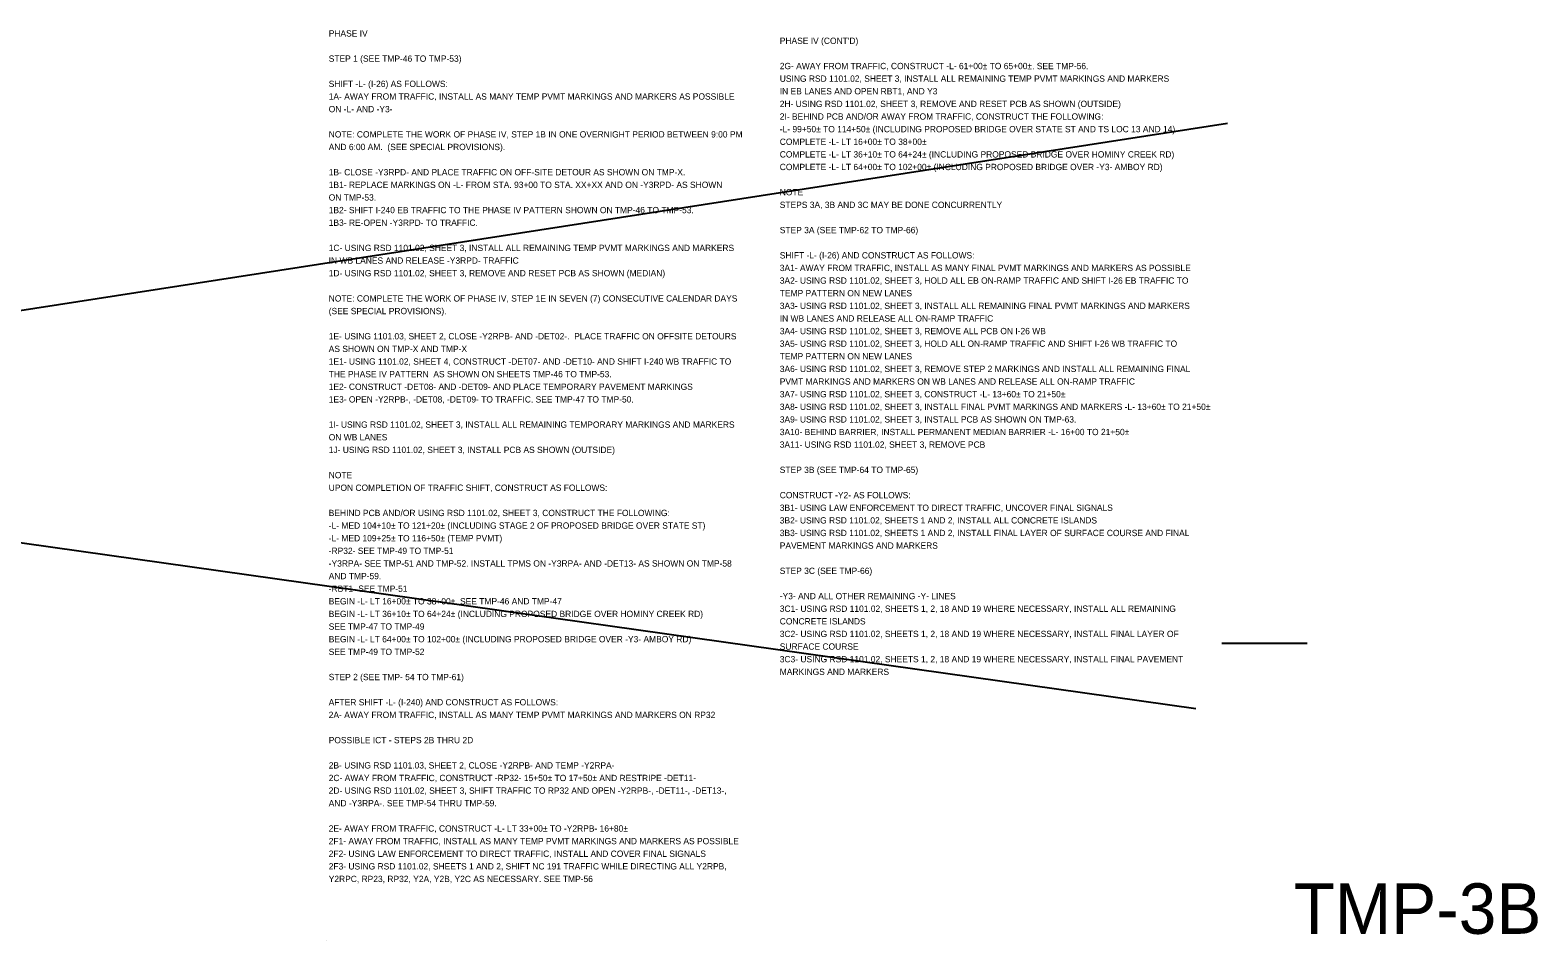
# Model space of a CAD drawing. Extents: x 2483905 to 2494512, y 366160 to 372330.
# Drawn here: x 2490709 to 2492380, y 371319 to 372330 of the extents above; entities that cross this region are included whole.
import ezdxf

# ---------------------------------------------------------------- set-up
doc = ezdxf.new("R2010")
doc.units = 0
doc.layers.add('TC SHEET BORDER LINE THIN', color=7, linetype='Continuous')
doc.layers.add('TC SHEET LAYOUT SHAPE', color=7, linetype='Continuous')

msp = doc.modelspace()

# ---------------------------------------------------------------- linework, layer by layer
at = {"layer": 'TC SHEET BORDER LINE THIN'}
for p, q in [((2486912.1, 372296.4), (2492000.8, 371577)), ((2486863.2, 371423.3), (2492035.7, 372226.5)), ((2492029.6, 371649.5), (2492124, 371649.5)), ((2491037.3, 371319.4), (2491037.3, 371319.4))]:
    msp.add_line(p, q, dxfattribs=at)

# ---------------------------------------------------------------- texts
for s, p in [('PHASE IV', (2491039.5, 372322.6)), ("PHASE IV (CONT'D)", (2491539.5, 372314.4)), ('STEP 1 (SEE TMP-46 TO TMP-53)', (2491039.5, 372294.6)), ('2G- AWAY FROM TRAFFIC, CONSTRUCT -L- 61+00± TO 65+00±. SEE TMP-56.', (2491539.5, 372286.4)), ('SHIFT -L- (I-26) AS FOLLOWS:', (2491039.5, 372266.6)), ('USING RSD 1101.02, SHEET 3, INSTALL ALL REMAINING TEMP PVMT MARKINGS AND MARKERS', (2491539.5, 372272.4)), ('1A- AWAY FROM TRAFFIC, INSTALL AS MANY TEMP PVMT MARKINGS AND MARKERS AS POSSIBLE', (2491039.5, 372252.6)), ('IN EB LANES AND OPEN RBT1, AND Y3', (2491539.5, 372258.4)), ('ON -L- AND -Y3-', (2491039.5, 372238.6)), ('2H- USING RSD 1101.02, SHEET 3, REMOVE AND RESET PCB AS SHOWN (OUTSIDE)', (2491539.5, 372244.4)), ('2I- BEHIND PCB AND/OR AWAY FROM TRAFFIC, CONSTRUCT THE FOLLOWING:', (2491539.5, 372230.4)), ('-L- 99+50± TO 114+50± (INCLUDING PROPOSED BRIDGE OVER STATE ST AND TS LOC 13 AND 14)', (2491539.5, 372216.4)), ('NOTE: COMPLETE THE WORK OF PHASE IV, STEP 1B IN ONE OVERNIGHT PERIOD BETWEEN 9:00 PM', (2491039.5, 372210.6)), ('COMPLETE -L- LT 16+00± TO 38+00±', (2491539.5, 372202.4)), ('AND 6:00 AM.  (SEE SPECIAL PROVISIONS).', (2491039.5, 372196.6)), ('COMPLETE -L- LT 36+10± TO 64+24± (INCLUDING PROPOSED BRIDGE OVER HOMINY CREEK RD)', (2491539.5, 372188.4)), ('1B- CLOSE -Y3RPD- AND PLACE TRAFFIC ON OFF-SITE DETOUR AS SHOWN ON TMP-X.', (2491039.5, 372168.6)), ('COMPLETE -L- LT 64+00± TO 102+00± (INCLUDING PROPOSED BRIDGE OVER -Y3- AMBOY RD)', (2491539.5, 372174.4)), ('1B1- REPLACE MARKINGS ON -L- FROM STA. 93+00 TO STA. XX+XX AND ON -Y3RPD- AS SHOWN', (2491039.5, 372154.6)), ('ON TMP-53.', (2491039.5, 372140.6)), ('NOTE', (2491539.5, 372146.4)), ('1B2- SHIFT I-240 EB TRAFFIC TO THE PHASE IV PATTERN SHOWN ON TMP-46 TO TMP-53.', (2491039.5, 372126.6)), ('STEPS 3A, 3B AND 3C MAY BE DONE CONCURRENTLY', (2491539.5, 372132.4)), ('1B3- RE-OPEN -Y3RPD- TO TRAFFIC.', (2491039.5, 372112.6)), ('STEP 3A (SEE TMP-62 TO TMP-66)', (2491539.5, 372104.4)), ('1C- USING RSD 1101.02, SHEET 3, INSTALL ALL REMAINING TEMP PVMT MARKINGS AND MARKERS', (2491039.5, 372084.6)), ('IN WB LANES AND RELEASE -Y3RPD- TRAFFIC', (2491039.5, 372070.6)), ('SHIFT -L- (I-26) AND CONSTRUCT AS FOLLOWS:', (2491539.5, 372076.4)), ('1D- USING RSD 1101.02, SHEET 3, REMOVE AND RESET PCB AS SHOWN (MEDIAN)', (2491039.5, 372056.6)), ('3A1- AWAY FROM TRAFFIC, INSTALL AS MANY FINAL PVMT MARKINGS AND MARKERS AS POSSIBLE', (2491539.5, 372062.4)), ('TEMP PATTERN ON NEW LANES', (2491539.5, 372034.4)), ('3A2- USING RSD 1101.02, SHEET 3, HOLD ALL EB ON-RAMP TRAFFIC AND SHIFT I-26 EB TRAFFIC TO', (2491539.5, 372048.4)), ('NOTE: COMPLETE THE WORK OF PHASE IV, STEP 1E IN SEVEN (7) CONSECUTIVE CALENDAR DAYS', (2491039.5, 372028.6)), ('3A3- USING RSD 1101.02, SHEET 3, INSTALL ALL REMAINING FINAL PVMT MARKINGS AND MARKERS', (2491539.5, 372020.4)), ('(SEE SPECIAL PROVISIONS).', (2491039.5, 372014.6)), ('IN WB LANES AND RELEASE ALL ON-RAMP TRAFFIC', (2491539.5, 372006.4)), ('1E- USING 1101.03, SHEET 2, CLOSE -Y2RPB- AND -DET02-.  PLACE TRAFFIC ON OFFSITE DETOURS', (2491039.5, 371986.6)), ('3A4- USING RSD 1101.02, SHEET 3, REMOVE ALL PCB ON I-26 WB', (2491539.5, 371992.4)), ('AS SHOWN ON TMP-X AND TMP-X ', (2491039.5, 371972.6)), ('3A5- USING RSD 1101.02, SHEET 3, HOLD ALL ON-RAMP TRAFFIC AND SHIFT I-26 WB TRAFFIC TO', (2491539.5, 371978.4)), ('1E1- USING 1101.02, SHEET 4, CONSTRUCT -DET07- AND -DET10- AND SHIFT I-240 WB TRAFFIC TO', (2491039.5, 371958.6)), ('TEMP PATTERN ON NEW LANES', (2491539.5, 371964.4)), ('3A6- USING RSD 1101.02, SHEET 3, REMOVE STEP 2 MARKINGS AND INSTALL ALL REMAINING FINAL', (2491539.5, 371950.4)), ('THE PHASE IV PATTERN  AS SHOWN ON SHEETS TMP-46 TO TMP-53.', (2491039.5, 371944.6)), ('PVMT MARKINGS AND MARKERS ON WB LANES AND RELEASE ALL ON-RAMP TRAFFIC', (2491539.5, 371936.4)), ('1E2- CONSTRUCT -DET08- AND -DET09- AND PLACE TEMPORARY PAVEMENT MARKINGS', (2491039.5, 371930.6)), ('1E3- OPEN -Y2RPB-, -DET08, -DET09- TO TRAFFIC. SEE TMP-47 TO TMP-50.', (2491039.5, 371916.6)), ('3A7- USING RSD 1101.02, SHEET 3, CONSTRUCT -L- 13+60± TO 21+50±', (2491539.5, 371922.4)), ('3A8- USING RSD 1101.02, SHEET 3, INSTALL FINAL PVMT MARKINGS AND MARKERS -L- 13+60± TO 21+50±', (2491539.5, 371908.4)), ('1I- USING RSD 1101.02, SHEET 3, INSTALL ALL REMAINING TEMPORARY MARKINGS AND MARKERS', (2491039.5, 371888.6)), ('3A9- USING RSD 1101.02, SHEET 3, INSTALL PCB AS SHOWN ON TMP-63.', (2491539.5, 371894.4)), ('ON WB LANES', (2491039.5, 371874.6)), ('3A10- BEHIND BARRIER, INSTALL PERMANENT MEDIAN BARRIER -L- 16+00 TO 21+50±', (2491539.5, 371880.4)), ('3A11- USING RSD 1101.02, SHEET 3, REMOVE PCB', (2491539.5, 371866.4)), ('1J- USING RSD 1101.02, SHEET 3, INSTALL PCB AS SHOWN (OUTSIDE)', (2491039.5, 371860.6)), ('NOTE', (2491039.5, 371832.6)), ('STEP 3B (SEE TMP-64 TO TMP-65)', (2491539.5, 371838.4)), ('UPON COMPLETION OF TRAFFIC SHIFT, CONSTRUCT AS FOLLOWS:', (2491039.5, 371818.6)), ('CONSTRUCT -Y2- AS FOLLOWS:', (2491539.5, 371810.4)), ('BEHIND PCB AND/OR USING RSD 1101.02, SHEET 3, CONSTRUCT THE FOLLOWING:', (2491039.5, 371790.6)), ('3B1- USING LAW ENFORCEMENT TO DIRECT TRAFFIC, UNCOVER FINAL SIGNALS', (2491539.5, 371796.4)), ('3B2- USING RSD 1101.02, SHEETS 1 AND 2, INSTALL ALL CONCRETE ISLANDS', (2491539.5, 371782.4)), ('-L- MED 104+10± TO 121+20± (INCLUDING STAGE 2 OF PROPOSED BRIDGE OVER STATE ST)', (2491039.5, 371776.6)), ('3B3- USING RSD 1101.02, SHEETS 1 AND 2, INSTALL FINAL LAYER OF SURFACE COURSE AND FINAL', (2491539.5, 371768.4)), ('-L- MED 109+25± TO 116+50± (TEMP PVMT)', (2491039.5, 371762.6)), ('-RP32- SEE TMP-49 TO TMP-51', (2491039.5, 371748.6)), ('PAVEMENT MARKINGS AND MARKERS', (2491539.5, 371754.4)), ('-Y3RPA- SEE TMP-51 AND TMP-52. INSTALL TPMS ON -Y3RPA- AND -DET13- AS SHOWN ON TMP-58', (2491039.5, 371734.6)), ('AND TMP-59.', (2491039.5, 371720.6)), ('STEP 3C (SEE TMP-66)', (2491539.5, 371726.4)), ('-RBT1- SEE TMP-51', (2491039.5, 371706.6)), ('-Y3- AND ALL OTHER REMAINING -Y- LINES', (2491539.5, 371698.4)), ('BEGIN -L- LT 16+00± TO 38+00±. SEE TMP-46 AND TMP-47', (2491039.5, 371692.6)), ('3C1- USING RSD 1101.02, SHEETS 1, 2, 18 AND 19 WHERE NECESSARY, INSTALL ALL REMAINING', (2491539.5, 371684.4)), ('BEGIN -L- LT 36+10± TO 64+24± (INCLUDING PROPOSED BRIDGE OVER HOMINY CREEK RD)', (2491039.5, 371678.6)), ('CONCRETE ISLANDS', (2491539.5, 371670.4)), ('SEE TMP-47 TO TMP-49', (2491039.5, 371664.6)), ('BEGIN -L- LT 64+00± TO 102+00± (INCLUDING PROPOSED BRIDGE OVER -Y3- AMBOY RD)', (2491039.5, 371650.6)), ('3C2- USING RSD 1101.02, SHEETS 1, 2, 18 AND 19 WHERE NECESSARY, INSTALL FINAL LAYER OF', (2491539.5, 371656.4)), ('SEE TMP-49 TO TMP-52', (2491039.5, 371636.6)), ('SURFACE COURSE', (2491539.5, 371642.4)), ('3C3- USING RSD 1101.02, SHEETS 1, 2, 18 AND 19 WHERE NECESSARY, INSTALL FINAL PAVEMENT', (2491539.5, 371628.4)), ('STEP 2 (SEE TMP- 54 TO TMP-61)', (2491039.5, 371608.6)), ('MARKINGS AND MARKERS', (2491539.5, 371614.4)), ('AFTER SHIFT -L- (I-240) AND CONSTRUCT AS FOLLOWS:', (2491039.5, 371580.6)), ('2A- AWAY FROM TRAFFIC, INSTALL AS MANY TEMP PVMT MARKINGS AND MARKERS ON RP32', (2491039.5, 371566.6)), ('POSSIBLE ICT - STEPS 2B THRU 2D', (2491039.5, 371538.6)), ('2B- USING RSD 1101.03, SHEET 2, CLOSE -Y2RPB- AND TEMP -Y2RPA-', (2491039.5, 371510.6)), ('2C- AWAY FROM TRAFFIC, CONSTRUCT -RP32- 15+50± TO 17+50± AND RESTRIPE -DET11-', (2491039.5, 371496.6)), ('2D- USING RSD 1101.02, SHEET 3, SHIFT TRAFFIC TO RP32 AND OPEN -Y2RPB-, -DET11-, -DET13-, ', (2491039.5, 371482.6)), ('AND -Y3RPA-. SEE TMP-54 THRU TMP-59.', (2491039.5, 371468.6)), ('2E- AWAY FROM TRAFFIC, CONSTRUCT -L- LT 33+00± TO -Y2RPB- 16+80±', (2491039.5, 371440.6)), ('2F1- AWAY FROM TRAFFIC, INSTALL AS MANY TEMP PVMT MARKINGS AND MARKERS AS POSSIBLE', (2491039.5, 371426.6)), ('2F2- USING LAW ENFORCEMENT TO DIRECT TRAFFIC, INSTALL AND COVER FINAL SIGNALS', (2491039.5, 371412.6)), ('2F3- USING RSD 1101.02, SHEETS 1 AND 2, SHIFT NC 191 TRAFFIC WHILE DIRECTING ALL Y2RPB,', (2491039.5, 371398.6)), ('Y2RPC, RP23, RP32, Y2A, Y2B, Y2C AS NECESSARY. SEE TMP-56', (2491039.5, 371384.6))]:
    msp.add_text(s, height=7, dxfattribs=at).set_placement(p)
at = {"layer": 'TC SHEET LAYOUT SHAPE'}
msp.add_text('TMP-3B', height=56, rotation=0.0001, dxfattribs=at).set_placement((2492109.2, 371327.2))

doc.saveas('drawing.dxf')
